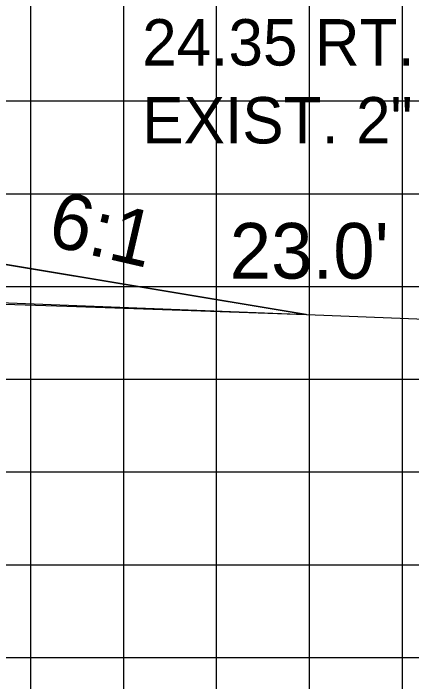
# Model space of a CAD drawing. Extents: x 859352 to 859522, y 366268 to 366378.
# Drawn here: x 859454.94 to 859459.23, y 366283.98 to 366291.18 of the extents above; entities that cross this region are included whole.
import ezdxf

# ---------------------------------------------------------------- set-up
doc = ezdxf.new("R2010")
doc.units = 0
for name, color, linetype in [('ANNOTATION', 7, 'Continuous'), ('D_Roadway_FinishedGrade', 7, 'Continuous'), ('D_Text_Monospaced', 7, 'Continuous'), ('D_Text_Standard', 7, 'Continuous'), ('JUNK FILL', 7, 'Continuous'), ('MAJOR', 7, 'Continuous'), ('MINOR', 7, 'Continuous'), ('S_Roadway_Centerline', 7, 'Continuous')]:
    doc.layers.add(name, color=color, linetype=linetype)

msp = doc.modelspace()

# ---------------------------------------------------------------- linework, layer by layer
at = {"layer": 'D_Roadway_FinishedGrade'}
msp.add_line((859453.5464, 366288.6915), (859458.0928, 366287.9337), dxfattribs=at)
at = {"layer": 'JUNK FILL'}
msp.add_lwpolyline([(859450.546, 366287.6271), (859451.1292, 366287.5766), (859452.1937, 366287.4843), (859453.1692, 366287.4751), (859453.8289, 366288.0766), (859455.515, 366288.0247), (859458.0928, 366287.9337), (859453.5464, 366288.6915), (859450.5462, 366288.7515)], close=True, dxfattribs=at)
at = {"layer": 'MAJOR'}
for p, q in [((859455.1294, 366277.2365), (859455.1294, 366297.2365)), ((859365.1294, 366287.2365), (859505.1294, 366287.2365))]:
    msp.add_line(p, q, dxfattribs=at)
at = {"layer": 'MINOR'}
for p, q in [((859456.1294, 366277.2365), (859456.1294, 366297.2365)), ((859457.1294, 366277.2365), (859457.1294, 366297.2365)), ((859458.1294, 366277.2365), (859458.1294, 366297.2365)), ((859459.1294, 366277.2365), (859459.1294, 366297.2365)), ((859365.1294, 366290.2365), (859505.1294, 366290.2365)), ((859365.1294, 366289.2365), (859505.1294, 366289.2365)), ((859365.1294, 366288.2365), (859505.1294, 366288.2365)), ((859365.1294, 366286.2365), (859505.1294, 366286.2365)), ((859365.1294, 366285.2365), (859505.1294, 366285.2365)), ((859365.1294, 366284.2365), (859505.1294, 366284.2365))]:
    msp.add_line(p, q, dxfattribs=at)
at = {"layer": 'S_Roadway_Centerline'}
msp.add_lwpolyline([(859406.4476, 366287.9895), (859414.4977, 366288.475), (859414.8625, 366288.5159), (859418.0236, 366288.4368), (859419.4455, 366288.4025), (859419.7817, 366288.3886), (859419.8076, 366288.3661), (859420.2709, 366287.8535), (859420.5704, 366287.8666), (859422.855, 366287.9873), (859424.3922, 366288.0745), (859424.9968, 366288.1014), (859426.1169, 366288.1231), (859435.8076, 366288.308), (859445.1105, 366288.0711), (859445.5475, 366288.0605), (859452.1937, 366287.4843), (859452.255, 366287.4811), (859453.1692, 366287.4751), (859453.8289, 366288.0766), (859453.8668, 366288.1002), (859456.7345, 366287.9871), (859463.9377, 366287.7043), (859477.1652, 366287.052)], dxfattribs=at)

# ---------------------------------------------------------------- texts
at = {"layer": 'ANNOTATION'}
msp.add_text('6:1', height=0.6, rotation=346.9679, dxfattribs=at).set_placement((859455.2889, 366288.688))
at = {"layer": 'D_Text_Monospaced'}
for s, p in [('24.35 RT.', (859456.3274, 366290.6189)), ('EXIST. 2" BOX ALDER', (859456.3274, 366289.7789))]:
    msp.add_text(s, height=0.49998, dxfattribs=at).set_placement(p)
at = {"layer": 'D_Text_Standard'}
msp.add_text("23.0'", height=0.6, dxfattribs=at).set_placement((859457.2699, 366288.3213))

doc.saveas('drawing.dxf')
